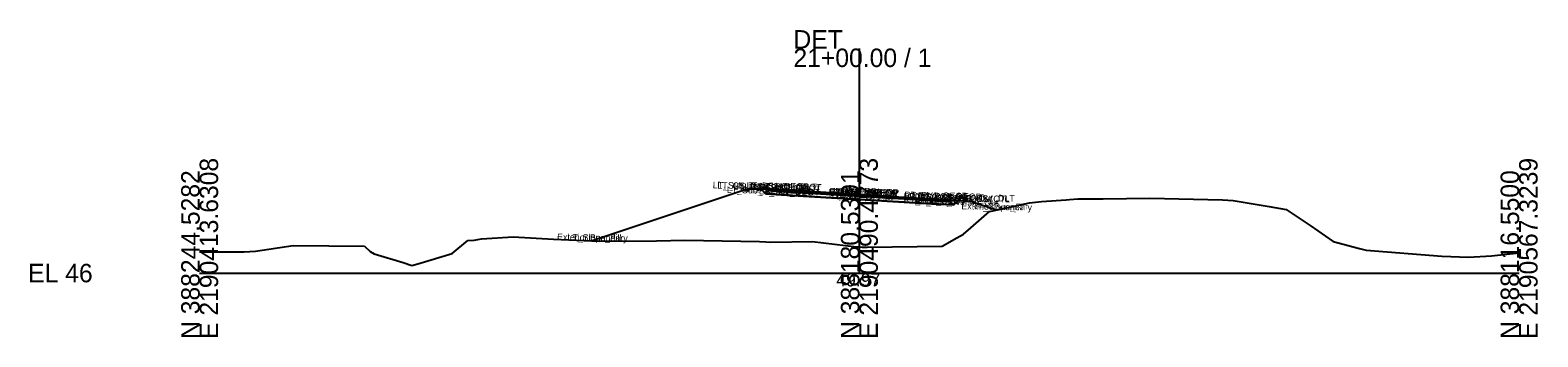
# Model space of a CAD drawing. Extents: x -26 to 1203, y -10 to 9543.
# Drawn here: x 974.3 to 1202.8, y 990.3 to 1036.9 of the extents above; entities that cross this region are included whole.
import ezdxf

# ---------------------------------------------------------------- set-up
doc = ezdxf.new("R2010")
doc.units = 0
for name, color, linetype in [('Default', 7, 'Continuous'), ('Exist Cross Section Cell', 7, 'Continuous'), ('Exist XS Center Line Elevation Label', 7, 'Continuous'), ('Exist XS Ground Line', 7, 'Continuous'), ('Prop CMT Pvmt Course 1', 7, 'Continuous'), ('Prop CMT Pvmt Course 2', 7, 'Continuous'), ('Prop CMT Pvmt Course 3', 7, 'Continuous'), ('Prop CMT Pvmt Surface', 7, 'Continuous'), ('Prop CMT Pvmt Surface Shoulder', 7, 'Continuous'), ('Prop CMT Shld Paved Course 1', 7, 'Continuous'), ('Prop CMT Shld Paved Course 2', 7, 'Continuous'), ('Prop CMT Shld Paved Course 3', 7, 'Continuous'), ('Prop CMT Slope Grass', 7, 'Continuous'), ('Prop CMT Subgrade Earthwork', 7, 'Continuous'), ('Scratch_Level_0', 7, 'Continuous')]:
    doc.layers.add(name, color=color, linetype=linetype)

msp = doc.modelspace()

# ---------------------------------------------------------------- linework, layer by layer
at = {"layer": 'Exist Cross Section Cell'}
for p, q in [((1100, 1000), (1100, 1034.08)), ((1000, 1000), (1100, 1000)), ((1100, 1000), (1200, 1000))]:
    msp.add_line(p, q, dxfattribs=at)
at = {"layer": 'Exist XS Ground Line'}
for p, q in [((1121.44, 1009.72), (1125.8, 1010.68)), ((1125.8, 1010.68), (1127.59, 1010.87)), ((1127.59, 1010.87), (1131.36, 1011.14)), ((1131.36, 1011.14), (1131.86, 1011.18)), ((1131.86, 1011.18), (1133.1, 1011.26)), ((1133.1, 1011.26), (1136.97, 1011.29)), ((1136.97, 1011.29), (1144.04, 1011.36)), ((1144.04, 1011.36), (1155.06, 1011.11)), ((1155.06, 1011.11), (1156.65, 1011.04)), ((1156.65, 1011.04), (1162.13, 1010.1)), ((1116.87, 1006.86), (1119.72, 1009.36)), ((1119.72, 1009.36), (1121.44, 1009.72)), ((1162.13, 1010.1), (1164.69, 1009.65)), ((1164.69, 1009.65), (1168.35, 1007.2)), ((1114.77, 1005.33), (1115.79, 1005.92)), ((1115.79, 1005.92), (1116.87, 1006.86)), ((1168.35, 1007.2), (1171.79, 1004.78)), ((1006.73, 1003.23), (1008.48, 1003.32)), ((1008.48, 1003.32), (1014.17, 1004.16)), ((1014.17, 1004.16), (1024.97, 1004.09)), ((1024.97, 1004.09), (1025.83, 1003.29)), ((1025.83, 1003.29), (1026.44, 1002.92)), ((1038.25, 1002.97), (1040.64, 1004.94)), ((1040.64, 1004.94), (1041.6, 1004.98)), ((1041.6, 1004.98), (1042.72, 1005.21)), ((1042.72, 1005.21), (1047.52, 1005.48)), ((1047.52, 1005.48), (1053.62, 1005.13)), ((1053.62, 1005.13), (1060.54, 1004.85)), ((1060.54, 1004.85), (1069.25, 1004.87)), ((1069.25, 1004.87), (1073.55, 1005)), ((1073.55, 1005), (1084.87, 1004.77)), ((1084.87, 1004.77), (1085.8, 1004.73)), ((1085.8, 1004.73), (1086.57, 1004.69)), ((1086.57, 1004.69), (1092.9, 1004.78)), ((1092.9, 1004.78), (1099.58, 1004)), ((1099.58, 1004), (1100, 1003.97)), ((1100, 1003.97), (1100.44, 1003.94)), ((1100.44, 1003.94), (1101.17, 1003.93)), ((1101.17, 1003.93), (1112.55, 1004.06)), ((1112.55, 1004.06), (1114.77, 1005.33)), ((1171.79, 1004.78), (1175.8, 1003.72)), ((1175.8, 1003.72), (1176.81, 1003.46)), ((1176.81, 1003.46), (1188.3, 1002.56)), ((1000, 1003.21), (1006.73, 1003.23)), ((1026.44, 1002.92), (1030.86, 1001.58)), ((1030.86, 1001.58), (1032.14, 1001.17)), ((1032.14, 1001.17), (1033.07, 1001.41)), ((1033.07, 1001.41), (1038.25, 1002.97)), ((1188.3, 1002.56), (1192.31, 1002.39)), ((1192.31, 1002.39), (1195.82, 1002.59)), ((1195.82, 1002.59), (1200, 1003.07))]:
    msp.add_line(p, q, dxfattribs=at)
at = {"layer": 'Prop CMT Pvmt Course 1'}
for points in [[(1100, 1011.94), (1089, 1012.6)], [(1089, 1012.6), (1089, 1012.35)], [(1089, 1012.35), (1100, 1011.69)], [(1100, 1011.69), (1100, 1011.94)], [(1100, 1011.94), (1111, 1011.28)], [(1100, 1011.69), (1100, 1011.94)], [(1111, 1011.03), (1100, 1011.69)], [(1111, 1011.28), (1111, 1011.03)]]:
    msp.add_lwpolyline(points, dxfattribs=at)
msp.add_lwpolyline([(1100, 1011.69), (1100, 1011.82), (1100, 1011.82), (1100, 1011.69)], close=True, dxfattribs=at)
msp.add_lwpolyline([(1100, 1011.69), (1100, 1011.82), (1100, 1011.82), (1100, 1011.69)], close=True, dxfattribs=at)
at = {"layer": 'Prop CMT Pvmt Course 2'}
for points in [[(1089, 1012.35), (1100, 1011.69)], [(1100, 1011.69), (1089, 1012.35)], [(1089, 1012.35), (1089, 1012.35)], [(1100, 1011.69), (1100, 1011.69)], [(1111, 1011.03), (1100, 1011.69)], [(1100, 1011.69), (1100, 1011.69)], [(1100, 1011.69), (1111, 1011.03)], [(1111, 1011.03), (1111, 1011.03)]]:
    msp.add_lwpolyline(points, dxfattribs=at)
at = {"layer": 'Prop CMT Pvmt Course 3'}
for points in [[(1100, 1011.69), (1089, 1012.35)], [(1089, 1012.35), (1089, 1011.85)], [(1089, 1011.85), (1100, 1011.19)], [(1100, 1011.19), (1100, 1011.69)], [(1100, 1011.69), (1111, 1011.03)], [(1100, 1011.19), (1100, 1011.69)], [(1111, 1010.53), (1100, 1011.19)], [(1111, 1011.03), (1111, 1010.53)]]:
    msp.add_lwpolyline(points, dxfattribs=at)
at = {"layer": 'Prop CMT Pvmt Surface'}
for points in [[(1100, 1011.94), (1089, 1012.6)], [(1100, 1011.94), (1111, 1011.28)]]:
    msp.add_lwpolyline(points, dxfattribs=at)
at = {"layer": 'Prop CMT Pvmt Surface Shoulder'}
for points in [[(1089, 1012.6), (1087, 1012.72)], [(1111, 1011.28), (1113, 1011.16)]]:
    msp.add_lwpolyline(points, dxfattribs=at)
at = {"layer": 'Prop CMT Shld Paved Course 1'}
for points in [[(1089, 1012.6), (1087, 1012.72), (1086.76, 1012.49)], [(1086.76, 1012.49), (1089, 1012.35)], [(1089, 1012.35), (1089, 1012.6)], [(1111, 1011.28), (1113, 1011.16), (1113.27, 1010.9)], [(1111, 1011.03), (1111, 1011.28)], [(1113.27, 1010.9), (1111, 1011.03)]]:
    msp.add_lwpolyline(points, dxfattribs=at)
at = {"layer": 'Prop CMT Shld Paved Course 2'}
for points in [[(1089, 1012.35), (1086.76, 1012.49)], [(1086.76, 1012.49), (1086.76, 1012.49)], [(1086.76, 1012.49), (1089, 1012.35)], [(1089, 1012.35), (1089, 1012.35)], [(1111, 1011.03), (1113.27, 1010.9)], [(1113.27, 1010.9), (1111, 1011.03)], [(1111, 1011.03), (1111, 1011.03)], [(1113.27, 1010.9), (1113.27, 1010.9)]]:
    msp.add_lwpolyline(points, dxfattribs=at)
at = {"layer": 'Prop CMT Shld Paved Course 3'}
for points in [[(1089, 1012.35), (1086.76, 1012.49), (1086.26, 1012.52), (1085.79, 1012.05)], [(1085.79, 1012.05), (1089, 1011.85)], [(1089, 1011.85), (1089, 1012.35)], [(1111, 1011.03), (1113.27, 1010.9), (1113.77, 1010.87), (1114.3, 1010.34)], [(1111, 1010.53), (1111, 1011.03)], [(1114.3, 1010.34), (1111, 1010.53)]]:
    msp.add_lwpolyline(points, dxfattribs=at)
at = {"layer": 'Prop CMT Slope Grass'}
for points in [[(1087, 1012.72), (1083, 1012.72), (1059.51, 1004.89)], [(1113, 1011.16), (1117, 1010.84), (1120.79, 1009.58)]]:
    msp.add_lwpolyline(points, dxfattribs=at)
at = {"layer": 'Prop CMT Subgrade Earthwork'}
for points in [[(1085.79, 1012.05), (1085.11, 1012.72)], [(1089, 1011.85), (1085.79, 1012.05)], [(1100, 1011.19), (1089, 1011.85)], [(1100, 1011.19), (1111, 1010.53)], [(1111, 1010.53), (1114.3, 1010.34)], [(1114.3, 1010.34), (1114.97, 1011.01)]]:
    msp.add_lwpolyline(points, dxfattribs=at)

# ---------------------------------------------------------------- texts
at = {"layer": 'Default'}
msp.add_text('-', height=0.0001, dxfattribs=at).set_placement((1000, 1000))
at = {"layer": 'Exist Cross Section Cell'}
for s, p in [('DET', (1090, 1034.08)), ('21+00.00 / 1', (1090, 1031.28)), ('EL 46', (974, 998.6))]:
    msp.add_text(s, height=2.8, dxfattribs=at).set_placement(p)
for s, p in [('E 2190413.6308', (1002.8, 990)), ('E 2190490.4773', (1102.8, 990)), ('E 2190567.3239', (1202.8, 990)), ('N 388244.5282', (1000, 990)), ('N 388180.5391', (1100, 990)), ('N 388116.5500', (1200, 990))]:
    msp.add_text(s, height=2.8, rotation=90, dxfattribs=at).set_placement(p)
at = {"layer": 'Exist XS Center Line Elevation Label'}
msp.add_text('49.97', height=2, dxfattribs=at).set_placement((1096.49, 997.97))
at = {"layer": 'Scratch_Level_0'}
for s, p in [('LT_Sub_Trench_Out_DLT', (1077.77, 1012.87)), ('LT_GS_OS_CTL', (1078.46, 1012.81)), ('LT_Sub_Trench_Out', (1079.9, 1012.16)), ('LT_PS3_Shelf_Out', (1080.92, 1012.62)), ('LT_PS3_OEOP', (1082.55, 1012.57)), ('LT_PS2_OEOP', (1082.55, 1012.57)), ('LT_PS1_OEOP', (1082.91, 1012.8)), ('LT_PV2_OEOT', (1084.75, 1012.44)), ('LT_PV3_OEOT', (1084.75, 1012.44)), ('LT_Sub_OEOT', (1084.77, 1011.94)), ('LT_PV1_OEOT', (1084.87, 1012.68)), ('RT_PV2_OEEOP', (1095.33, 1011.78)), ('RT_PV3_OEEOP', (1095.33, 1011.78)), ('LT_PV2_OEEOP', (1095.39, 1011.78)), ('LT_PV3_OEEOP', (1095.39, 1011.78)), ('RT_PV1_OEEOP', (1095.45, 1011.91)), ('LT_PV1_OEEOP', (1095.51, 1011.91)), ('RT_PV2_IEEOP', (1095.71, 1011.78)), ('LT_PV2_IEEOP', (1095.77, 1011.78)), ('RT_PV1_IEEOP', (1095.83, 1011.9)), ('LT_PV1_IEEOP', (1095.89, 1011.9)), ('PV2_PGL', (1097.35, 1011.74)), ('PV1_PGL', (1097.47, 1011.99)), ('RT_Sub_OEEOP', (1095.36, 1011.28)), ('LT_Sub_OEEOP', (1095.42, 1011.28)), ('RT_PV3_OEOT', (1106.69, 1011.12)), ('RT_PV2_OEOT', (1106.69, 1011.12)), ('RT_Sub_OEOT', (1106.71, 1010.62)), ('RT_PV1_OEOT', (1106.81, 1011.36)), ('RT_Sub_Trench_Out_DLT', (1107.56, 1011.15)), ('RT_Sub_Trench_Out', (1108.35, 1010.45)), ('RT_PS3_Shelf_Out', (1108.37, 1010.97)), ('RT_PS1_OEOP', (1108.85, 1011.24)), ('RT_PS3_OEOP', (1108.99, 1010.98)), ('RT_PS2_OEOP', (1108.99, 1010.98)), ('RT_GS_OS_CTL', (1112.41, 1010.93)), ('Exterior Boundary', (1115.45, 1009.69)), ('RT_Slope_Fill', (1116.97, 1009.66)), ('Exterior Boundary', (1054.17, 1005)), ('LT_Slope_Fill', (1055.74, 1004.97))]:
    msp.add_text(s, height=1, rotation=358.8836, dxfattribs=at).set_placement(p)

doc.saveas('drawing.dxf')
